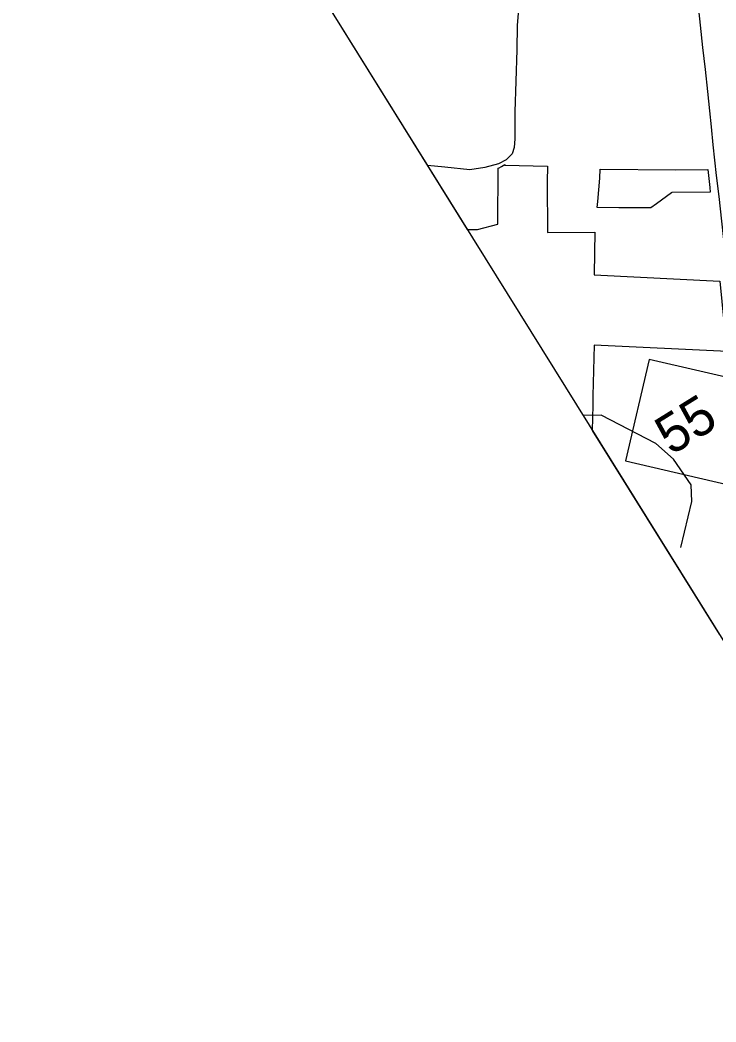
# Model space of a CAD drawing. Extents: x 2001466 to 31450019, y -30647475 to 847247.
# Drawn here: x 31418162 to 31424456, y -30647475 to -30638422 of the extents above; entities that cross this region are included whole.
import ezdxf

# ---------------------------------------------------------------- set-up
doc = ezdxf.new("R2010")
doc.units = 0
for name, color, linetype in [('Exist Boundary Political City Limit New', 7, 'Continuous'), ('Exist Boundary Political City Limit New Hole', 7, 'Continuous'), ('Exist Hydrographic Creek Single Shore', 7, 'Continuous'), ('Exist Road Primary NC Shield CELL', 7, 'Continuous'), ('Exist Road Primary NC Shield Number Label', 7, 'Continuous'), ('Exist Road Primary NC UnDivided 4 Lane Attributed', 7, 'Continuous'), ('Exist Road Secondary Type 51 Attributed', 7, 'Continuous'), ('Map Preparation Boundary City Limit Buffer Line', 7, 'Continuous')]:
    doc.layers.add(name, color=color, linetype=linetype)

msp = doc.modelspace()

# ---------------------------------------------------------------- linework, layer by layer
at = {"layer": 'Exist Boundary Political City Limit New'}
msp.add_line((31418162.3, -30633820.8), (31426666.7, -30647475), dxfattribs=at)
msp.add_lwpolyline([(31423407.9, -30639768.1), (31424093.8, -30639774.1), (31424381.9, -30639771.6), (31424400.1, -30639935.7), (31424404.5, -30639975.8), (31424057.4, -30639978.5), (31424052.6, -30639982), (31423916.8, -30640083), (31423867.5, -30640119.6), (31423577.9, -30640117.1), (31423381.5, -30640115.5), (31423386.3, -30640060.8), (31423404.5, -30639849.3), (31423407.9, -30639768.1)], dxfattribs=at)
at = {"layer": 'Exist Boundary Political City Limit New Hole'}
for p, q in [((31420678.9, -30637861.3), (31422206.6, -30640314.1)), ((31423337.1, -30642129.2), (31424485.1, -30643972.3))]:
    msp.add_line(p, q, dxfattribs=at)
for points in [[(31422206.6, -30640314.1), (31422298.1, -30640313.8), (31422483.3, -30640267), (31422486.6, -30639759.5), (31422496.3, -30639755.9), (31422516.8, -30639745.6), (31422547.4, -30639728.1), (31422547.4, -30639732.8), (31422933.1, -30639743.3), (31422930.5, -30639884.9), (31422932.3, -30640342.3), (31423361.5, -30640338.4), (31423358, -30640523.4), (31423354.1, -30640723.4)], [(31423354.1, -30640723.4), (31424489.9, -30640781.1), (31424527.6, -30641147.8), (31424558.8, -30641418), (31423353.6, -30641358.6), (31423342.8, -30641816), (31423342.6, -30641817.5), (31423341, -30641901.4), (31423337.1, -30642129.2)]]:
    msp.add_lwpolyline(points, dxfattribs=at)
at = {"layer": 'Exist Hydrographic Creek Single Shore'}
for points in [[(31423911.4, -30642248), (31423418.7, -30641992.1), (31423253.9, -30641995.6)], [(31424139.6, -30643188), (31424238.7, -30642773.4), (31424230.7, -30642622.3), (31424071.6, -30642389.4), (31423911.4, -30642248)]]:
    msp.add_lwpolyline(points, dxfattribs=at)
at = {"layer": 'Exist Road Primary NC Shield CELL'}
msp.add_lwpolyline([(31424556.4, -30642618.3), (31424769.6, -30641700.9), (31423852.2, -30641487.7), (31423639, -30642405.1), (31424556.4, -30642618.3)], dxfattribs=at)
at = {"layer": 'Exist Road Primary NC UnDivided 4 Lane Attributed'}
msp.add_lwpolyline([(31424905.9, -30643922.8), (31424855.6, -30643460.2), (31424811.8, -30643051.4), (31424758, -30642545.7), (31424735, -30642339), (31424713.8, -30642139.9), (31424653.5, -30641574.3), (31424601.3, -30641107.1), (31424571.7, -30640818.1), (31424541.8, -30640543), (31424509.5, -30640240.2), (31424484.9, -30640017.4), (31424461.1, -30639826.8), (31424431.9, -30639547.8), (31424414.3, -30639386.5), (31424400.5, -30639243.5), (31424381.3, -30639066), (31424360.1, -30638870), (31424337.1, -30638669.5), (31424315.6, -30638468.1), (31424291, -30638242.2), (31424270.3, -30638039.3), (31424243.4, -30637800.3), (31424220.4, -30637608)], dxfattribs=at)
at = {"layer": 'Exist Road Secondary Type 51 Attributed'}
msp.add_lwpolyline([(31422782.1, -30637891.6), (31422772, -30638007.5), (31422747.9, -30638083.2), (31422710.9, -30638139.6), (31422680.3, -30638255.5), (31422665.8, -30638360.2), (31422659.4, -30638471.3), (31422655.8, -30638690.3), (31422645.3, -30638975.3), (31422637.7, -30639252.3), (31422636.1, -30639494.6), (31422631.3, -30639573.5), (31422611.9, -30639631.5), (31422558.4, -30639683.8), (31422489.2, -30639722.4), (31422367, -30639755.5), (31422230.2, -30639774.8), (31422004.9, -30639752.2), (31421846.3, -30639735.6)], dxfattribs=at)
at = {"layer": 'Map Preparation Boundary City Limit Buffer Line'}
for p, q in [((31418162.3, -30633820.8), (31426666.7, -30647475)), ((31420678.9, -30637861.3), (31422206.6, -30640314.1)), ((31423337.1, -30642129.2), (31424485.1, -30643972.3))]:
    msp.add_line(p, q, dxfattribs=at)
for points in [[(31422206.6, -30640314.1), (31422298.1, -30640313.8), (31422483.3, -30640267), (31422486.6, -30639759.5), (31422496.3, -30639755.9), (31422516.8, -30639745.6), (31422547.4, -30639728.1), (31422547.4, -30639732.8), (31422933.1, -30639743.3), (31422930.5, -30639884.9), (31422932.3, -30640342.3), (31423361.5, -30640338.4), (31423358, -30640523.4), (31423354.1, -30640723.4)], [(31423407.9, -30639768.1), (31424093.8, -30639774.1), (31424381.9, -30639771.6), (31424400.1, -30639935.7), (31424404.5, -30639975.8), (31424057.4, -30639978.5), (31424052.6, -30639982), (31423916.8, -30640083), (31423867.5, -30640119.6), (31423577.9, -30640117.1), (31423381.5, -30640115.5), (31423386.3, -30640060.8), (31423404.5, -30639849.3), (31423407.9, -30639768.1)], [(31423354.1, -30640723.4), (31424489.9, -30640781.1), (31424527.6, -30641147.8), (31424558.8, -30641418), (31423353.6, -30641358.6), (31423342.8, -30641816), (31423342.6, -30641817.5), (31423341, -30641901.4), (31423337.1, -30642129.2)]]:
    msp.add_lwpolyline(points, dxfattribs=at)

# ---------------------------------------------------------------- texts
at = {"layer": 'Exist Road Primary NC Shield Number Label'}
msp.add_text('55', height=350, rotation=31.91803, dxfattribs=at).set_placement((31424051.5, -30642359.6))

doc.saveas('drawing.dxf')
